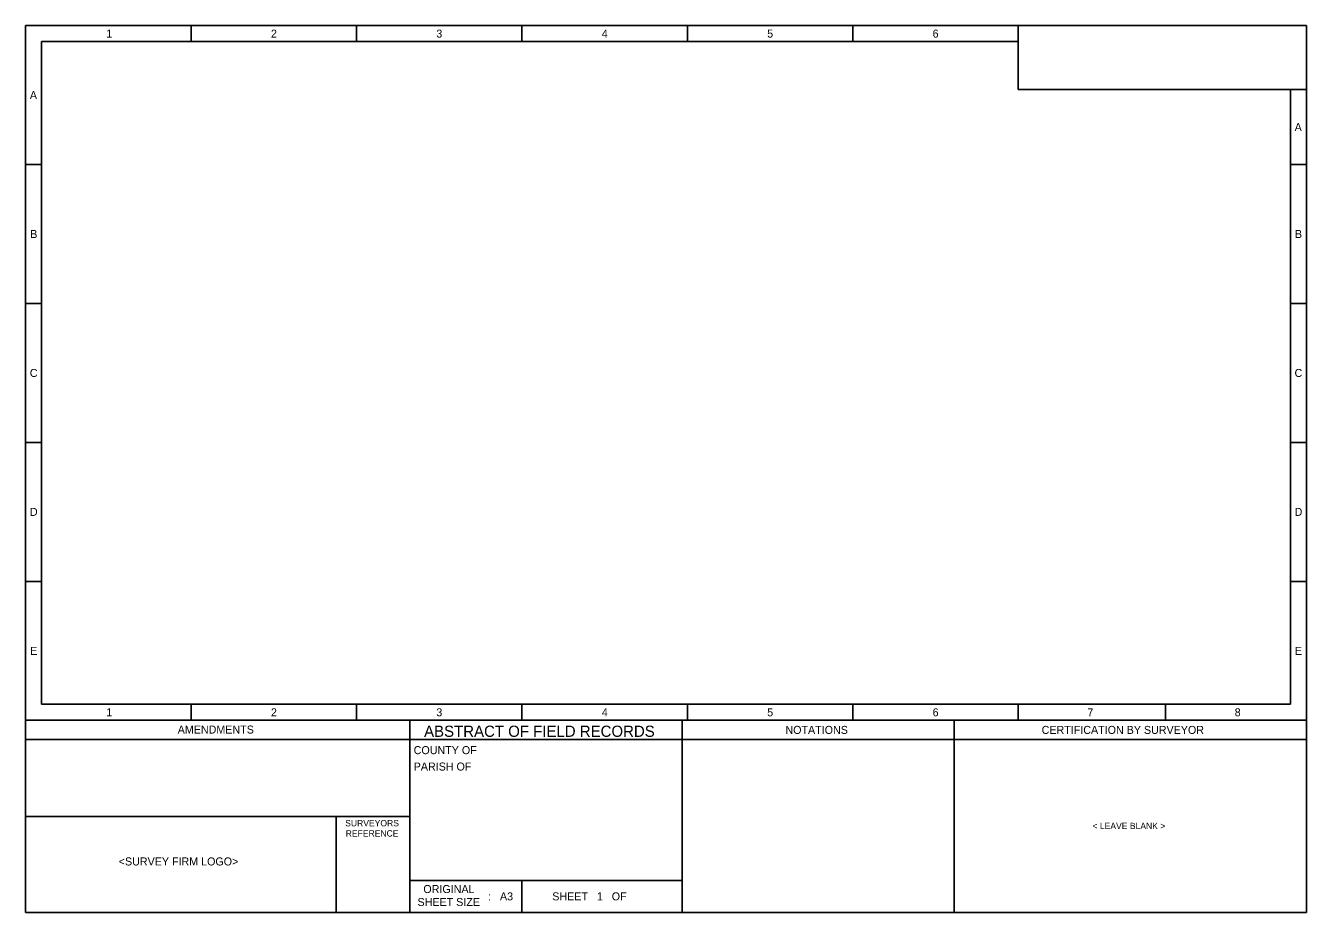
# Model space of a CAD drawing. Extents: x 0.01 to 0.41, y 0.01 to 0.287.
import ezdxf

# ---------------------------------------------------------------- set-up
doc = ezdxf.new("R2010")
doc.units = 0
for name, color, linetype in [('Proforma major line', 7, 'Continuous'), ('Proforma minor line', 7, 'Continuous'), ('Proforma text', 7, 'Continuous')]:
    doc.layers.add(name, color=color, linetype=linetype)

msp = doc.modelspace()

# ---------------------------------------------------------------- linework, layer by layer
at = {"layer": 'Proforma major line'}
for p, q in [((0.01, 0.01), (0.01, 0.287)), ((0.41, 0.287), (0.01, 0.287)), ((0.41, 0.01), (0.41, 0.287)), ((0.01, 0.07), (0.41, 0.07)), ((0.01, 0.01), (0.41, 0.01))]:
    msp.add_line(p, q, dxfattribs=at)
at = {"layer": 'Proforma minor line'}
for p, q in [((0.06167, 0.287), (0.06167, 0.282)), ((0.11333, 0.287), (0.11333, 0.282)), ((0.165, 0.287), (0.165, 0.282)), ((0.21667, 0.287), (0.21667, 0.282)), ((0.26833, 0.287), (0.26833, 0.282)), ((0.32, 0.287), (0.32, 0.267)), ((0.32, 0.282), (0.015, 0.282)), ((0.015, 0.075), (0.015, 0.282)), ((0.32, 0.267), (0.41, 0.267)), ((0.405, 0.075), (0.405, 0.267)), ((0.015, 0.2436), (0.01, 0.2436)), ((0.41, 0.2436), (0.405, 0.2436)), ((0.015, 0.2002), (0.01, 0.2002)), ((0.41, 0.2002), (0.405, 0.2002)), ((0.015, 0.1568), (0.01, 0.1568)), ((0.41, 0.1568), (0.405, 0.1568)), ((0.015, 0.1134), (0.01, 0.1134)), ((0.41, 0.1134), (0.405, 0.1134)), ((0.015, 0.075), (0.405, 0.075)), ((0.06167, 0.075), (0.06167, 0.07)), ((0.11333, 0.075), (0.11333, 0.07)), ((0.165, 0.075), (0.165, 0.07)), ((0.21667, 0.075), (0.21667, 0.07)), ((0.26833, 0.075), (0.26833, 0.07)), ((0.32, 0.075), (0.32, 0.07)), ((0.366, 0.075), (0.366, 0.07)), ((0.13, 0.01), (0.13, 0.07)), ((0.215, 0.01), (0.215, 0.07)), ((0.3, 0.01), (0.3, 0.07)), ((0.01, 0.064), (0.13, 0.064)), ((0.13, 0.064), (0.23, 0.064)), ((0.23, 0.064), (0.41, 0.064)), ((0.01, 0.04), (0.13, 0.04)), ((0.107, 0.01), (0.107, 0.04)), ((0.13, 0.02), (0.215, 0.02)), ((0.165, 0.01), (0.165, 0.02))]:
    msp.add_line(p, q, dxfattribs=at)

# ---------------------------------------------------------------- texts
at = {"layer": 'Proforma text'}
for s, height, p in [('1', 0.0025, (0.03518, 0.28325)), ('2', 0.0025, (0.08662, 0.28325)), ('3', 0.0025, (0.13827, 0.28325)), ('4', 0.0025, (0.18995, 0.28325)), ('5', 0.0025, (0.2416, 0.28325)), ('6', 0.0025, (0.29327, 0.28325)), ('A', 0.0025, (0.01133, 0.26405)), ('A', 0.0025, (0.40633, 0.25405)), ('B', 0.0025, (0.01143, 0.22065)), ('B', 0.0025, (0.40643, 0.22065)), ('C', 0.0025, (0.01131, 0.17725)), ('C', 0.0025, (0.40631, 0.17725)), ('D', 0.0025, (0.01133, 0.13385)), ('D', 0.0025, (0.40633, 0.13385)), ('E', 0.0025, (0.01143, 0.09045)), ('E', 0.0025, (0.40643, 0.09045)), ('1', 0.0025, (0.03518, 0.07125)), ('2', 0.0025, (0.08662, 0.07125)), ('3', 0.0025, (0.13827, 0.07125)), ('4', 0.0025, (0.18995, 0.07125)), ('5', 0.0025, (0.2416, 0.07125)), ('6', 0.0025, (0.29327, 0.07125)), ('7', 0.0025, (0.34161, 0.07125)), ('8', 0.0025, (0.38761, 0.07125)), ('AMENDMENTS', 0.0025, (0.0575, 0.06586)), ('ABSTRACT OF FIELD RECORDS', 0.0035, (0.13445, 0.06483)), ('NOTATIONS', 0.0025, (0.2473, 0.06575)), ('CERTIFICATION BY SURVEYOR', 0.0025, (0.32732, 0.06575)), ('COUNTY OF ', 0.0025, (0.1312, 0.05943)), ('PARISH OF ', 0.0025, (0.1312, 0.05431)), ('SURVEYORS', 0.002, (0.1098, 0.03688)), ('< LEAVE BLANK >', 0.002, (0.3432, 0.036)), ('REFERENCE', 0.002, (0.10996, 0.03368)), ('<SURVEY FIRM LOGO>', 0.0025, (0.03909, 0.02466)), ('ORIGINAL', 0.0025, (0.13422, 0.01604)), (':   A3', 0.0025, (0.15443, 0.01375)), ('SHEET   1   OF       ', 0.0025, (0.17448, 0.01375)), ('SHEET SIZE', 0.0025, (0.1324, 0.01198))]:
    msp.add_text(s, height=height, dxfattribs=at).set_placement(p)

doc.saveas('drawing.dxf')
